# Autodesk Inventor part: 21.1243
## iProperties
Created: 2006-02
Part Number: 21.1243
Material: Steel, Mild
Description: M6 x 30 SHCS
Document SubType Name: Modeling
Standard: DIN 7984
Designer: Andy Moles
Standards Organization: DIN
Language: en-US
Size Designation: M6 x 30
Categories: <MemberInstance><Categories><Category DisplayName="Fasteners" InternalName="e4da775c-781d-43d5-af7c-5136215cf5a6" Mnemonic="FSTN"><Category DisplayName="Bolts"
Density: 7.86 g/cm^3
Vendor: S
Mass: 8.70818 g
Surface Area: 8.78056 cm^2
Volume: 1.10791 cm^3
Author: Andy Moles
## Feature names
1. Body [Revolution]
2. Slot [Extrusion]
3. Fillet1
4. Chamfer1
